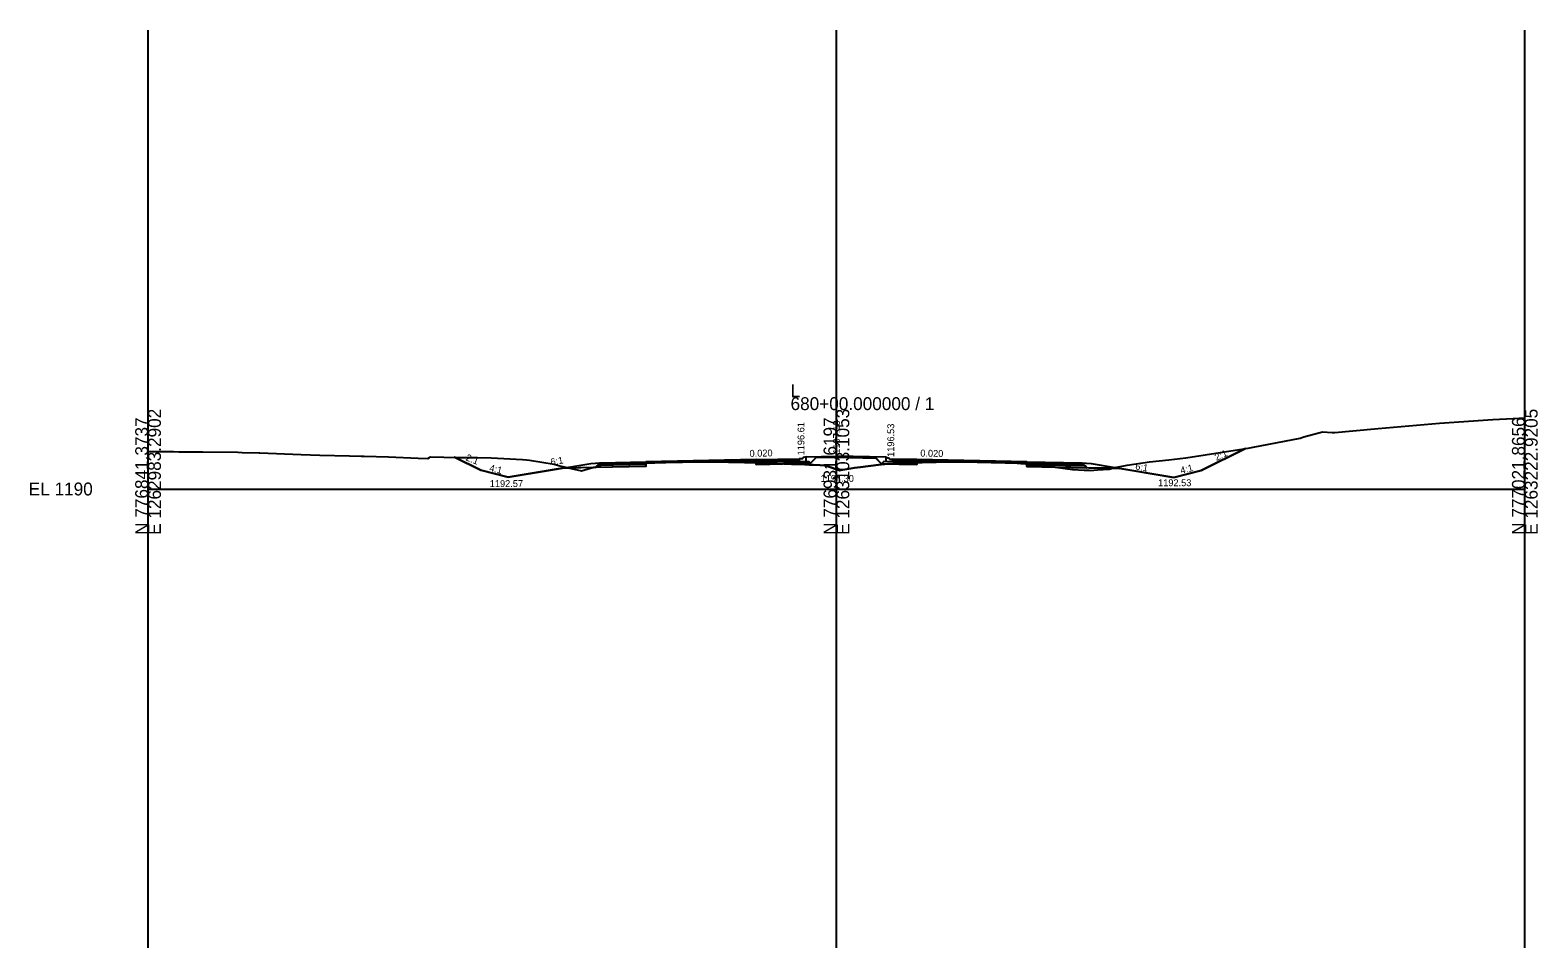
# Model space of a CAD drawing. Extents: x -41 to 1262860, y -100 to 777489.
# Drawn here: x 474.3 to 802.8, y 3185 to 3385 of the extents above; entities that cross this region are included whole.
import ezdxf

# ---------------------------------------------------------------- set-up
doc = ezdxf.new("R2010")
doc.units = 0
for name, color, linetype in [('Exist Cross Section Cell', 7, 'Continuous'), ('Exist XS Center Line Elevation Label', 7, 'Continuous'), ('Exist XS Ground Line', 7, 'Continuous'), ('Prop CMT Pvmt Course 1', 7, 'Continuous'), ('Prop CMT Pvmt Surface', 7, 'Continuous'), ('Prop CMT Shld Paved Course 1', 7, 'Continuous'), ('Prop CMT Shld Paved Course 2', 7, 'Continuous'), ('Prop CMT Shld Paved Course 4', 7, 'Continuous'), ('Prop CMT Subgrade Earthwork', 7, 'Continuous'), ('Prop Conc Curb and Gutter', 7, 'Continuous'), ('Prop Conc Island Cover', 7, 'Continuous'), ('Prop XS Ditch Standard Text', 7, 'Continuous'), ('Prop XS Earthwork Shape', 7, 'Continuous'), ('Prop XS Elevation Labels', 7, 'Continuous'), ('Prop XS Exc Vertical Line 1', 7, 'Continuous'), ('Prop XS Exc Vertical Line 2', 7, 'Continuous'), ('Prop XS Exc Vertical Line 3', 7, 'Continuous'), ('Prop XS Finish Grade', 7, 'Continuous'), ('Prop XS Hydro Elevations', 7, 'Continuous'), ('Prop XS SE Text', 7, 'Continuous'), ('Prop XS Side Slope Text', 7, 'Continuous'), ('Scratch_Level_4', 7, 'Continuous'), ('Scratch_Level_6', 7, 'Continuous')]:
    doc.layers.add(name, color=color, linetype=linetype)

msp = doc.modelspace()

# ---------------------------------------------------------------- linework, layer by layer
at = {"layer": 'Exist Cross Section Cell'}
for p, q in [((650, 3285), (650, 3305)), ((500, 3285), (650, 3285)), ((650, 3285), (800, 3285))]:
    msp.add_line(p, q, dxfattribs=at)
at = {"layer": 'Exist XS Ground Line'}
msp.add_lwpolyline([(500, 3293.17), (501.1, 3293.15), (502.01, 3293.14), (505.54, 3293.14), (506.73, 3293.13), (511.94, 3293.1), (519.57, 3293), (520.5, 3292.98), (524.21, 3292.89), (524.36, 3292.89), (533.39, 3292.5), (537.45, 3292.4), (543.89, 3292.26), (546.44, 3292.18), (547.08, 3292.16), (552.41, 3292.04), (558.87, 3291.75), (560.93, 3291.64), (561.35, 3291.9), (561.57, 3292.04), (567.36, 3291.9), (568.85, 3291.87), (569.19, 3291.86), (569.58, 3291.85), (571.79, 3291.83), (574.77, 3291.79), (581.6, 3291.44), (582.44, 3291.39), (583.1, 3291.3), (588.46, 3290.39), (589.76, 3290.03), (594.48, 3288.95), (595.92, 3289.38), (597.64, 3289.81), (599.6, 3290.57), (599.81, 3290.64), (600.51, 3290.63), (604.74, 3290.51), (605.11, 3290.43), (605.2, 3290.4), (609.59, 3290.73), (610.44, 3290.8), (612.8, 3290.84), (622.95, 3290.94), (631.36, 3290.74), (635.36, 3290.64), (640.2, 3290.43), (642.18, 3290.38), (644.08, 3290.3), (644.9, 3290.27), (646.48, 3290.18), (647.38, 3290.12), (647.97, 3289.95), (650.77, 3289.06), (651.4, 3289.2), (653.12, 3289.48), (653.92, 3289.63), (655.24, 3289.74), (659.16, 3290.28), (661.23, 3290.5), (664.55, 3290.67), (665.55, 3290.72), (674.84, 3290.89), (677.62, 3290.93), (686.8, 3290.69), (689.36, 3290.63), (690.18, 3290.58), (693.21, 3290.36), (695.59, 3290.03), (697.76, 3289.75), (699.84, 3289.47), (701.43, 3289.27), (703.96, 3289.12), (705, 3289.07), (705.3, 3289.05), (706.89, 3289.2), (709.41, 3289.34), (710.74, 3289.66), (713.33, 3290.21), (718.22, 3290.89), (722.45, 3291.37), (726.12, 3291.78), (738.75, 3293.79), (739.75, 3293.93), (740.83, 3294.14), (751.05, 3296.1), (751.87, 3296.34), (755.9, 3297.45), (758, 3297.34), (758.62, 3297.31), (762.55, 3297.69), (768.07, 3298.17), (781.4, 3299.34), (793.03, 3300.16), (797.48, 3300.36), (800, 3300.48)], dxfattribs=at)
at = {"layer": 'Prop CMT Pvmt Course 1'}
for p, q in [((632.5, 3291.16), (641.89, 3291.35)), ((641.89, 3291.35), (641.89, 3291.6)), ((662.3, 3291.51), (662.3, 3291.26)), ((667.5, 3291.16), (662.3, 3291.26))]:
    msp.add_line(p, q, dxfattribs=at)
for points in [[(608.5, 3290.93), (608.5, 3290.68), (632.5, 3291.16), (632.5, 3291.16), (632.5, 3291.41), (632.5, 3291.41), (632.5, 3291.41), (608.5, 3290.93), (608.5, 3290.93)], [(691.5, 3290.93), (691.5, 3290.93), (667.5, 3291.41), (667.5, 3291.41), (667.5, 3291.41), (667.5, 3291.16), (667.5, 3291.16), (691.5, 3290.68), (691.5, 3290.93)]]:
    msp.add_lwpolyline(points, dxfattribs=at)
at = {"layer": 'Prop CMT Pvmt Surface'}
for p, q in [((598.5, 3290.73), (608.5, 3290.93)), ((608.5, 3290.93), (632.5, 3291.41)), ((632.5, 3291.41), (641.89, 3291.6)), ((667.5, 3291.41), (662.3, 3291.51)), ((667.5, 3291.41), (691.5, 3290.93)), ((691.5, 3290.93), (703.5, 3290.69))]:
    msp.add_line(p, q, dxfattribs=at)
at = {"layer": 'Prop CMT Shld Paved Course 1'}
for p, q in [((598.24, 3290.47), (598.5, 3290.73)), ((608.5, 3290.68), (598.24, 3290.47)), ((604.5, 3290.85), (604.5, 3290.85)), ((608.5, 3290.93), (608.5, 3290.93)), ((608.5, 3290.93), (608.5, 3290.93)), ((608.5, 3290.93), (608.5, 3290.68)), ((608.5, 3290.68), (608.5, 3290.68)), ((691.5, 3290.93), (691.5, 3290.93)), ((691.5, 3290.93), (691.5, 3290.93)), ((691.5, 3290.93), (691.5, 3290.68)), ((691.5, 3290.68), (691.5, 3290.68)), ((691.5, 3290.68), (703.76, 3290.43)), ((695.5, 3290.85), (695.5, 3290.85)), ((703.76, 3290.43), (703.5, 3290.69))]:
    msp.add_line(p, q, dxfattribs=at)
at = {"layer": 'Prop CMT Shld Paved Course 2'}
for p, q in [((597.9, 3290.13), (598.24, 3290.47)), ((608.5, 3290.35), (597.9, 3290.13)), ((604.25, 3290.59), (604.25, 3290.59)), ((609.59, 3290.7), (608.5, 3290.68)), ((608.5, 3290.65), (609.05, 3290.69)), ((608.5, 3290.68), (608.5, 3290.68)), ((608.5, 3290.68), (608.5, 3290.68)), ((608.5, 3290.68), (608.5, 3290.35)), ((608.5, 3290.68), (608.5, 3290.68)), ((608.5, 3290.68), (608.5, 3290.65)), ((608.5, 3290.65), (608.5, 3290.65)), ((608.5, 3290.35), (608.5, 3290.35)), ((609.05, 3290.69), (609.59, 3290.7)), ((609.05, 3290.69), (609.05, 3290.69)), ((610.44, 3290.72), (609.59, 3290.7)), ((609.59, 3290.7), (610.44, 3290.72)), ((609.59, 3290.7), (609.59, 3290.7)), ((609.59, 3290.7), (609.59, 3290.7)), ((612.8, 3290.76), (610.44, 3290.72)), ((610.44, 3290.72), (612.8, 3290.76)), ((622.95, 3290.97), (612.8, 3290.76)), ((612.8, 3290.76), (619.95, 3290.91)), ((612.8, 3290.76), (612.8, 3290.76)), ((612.8, 3290.76), (612.8, 3290.76)), ((619.95, 3290.91), (622.95, 3290.94)), ((619.95, 3290.91), (619.95, 3290.91)), ((619.95, 3290.91), (619.95, 3290.91)), ((631.36, 3291.14), (622.95, 3290.97)), ((622.95, 3290.97), (622.95, 3290.97)), ((622.95, 3290.97), (622.95, 3290.97)), ((622.95, 3290.94), (622.95, 3290.94)), ((622.95, 3290.94), (629.95, 3290.77)), ((629.95, 3290.77), (631.36, 3290.8)), ((629.95, 3290.77), (629.95, 3290.77)), ((632.5, 3291.16), (631.36, 3291.14)), ((631.36, 3291.14), (631.36, 3291.14)), ((631.36, 3290.8), (632.5, 3290.83)), ((631.36, 3290.8), (631.36, 3290.8)), ((632.5, 3290.83), (632.5, 3291.16)), ((632.5, 3291.16), (632.5, 3291.16)), ((632.5, 3290.82), (641.89, 3291.01)), ((641.89, 3291.35), (641.89, 3291.01)), ((641.89, 3291.01), (641.89, 3291.01)), ((662.3, 3290.93), (662.3, 3291.26)), ((667.5, 3290.83), (662.3, 3290.93)), ((667.5, 3290.83), (667.5, 3291.16)), ((667.5, 3291.16), (667.5, 3291.16)), ((667.5, 3291.16), (667.5, 3291.16)), ((667.5, 3291.16), (674.84, 3291.01)), ((669.28, 3290.79), (667.5, 3290.83)), ((667.5, 3290.83), (667.5, 3290.83)), ((674.84, 3290.89), (669.28, 3290.79)), ((669.28, 3290.79), (669.28, 3290.79)), ((674.84, 3291.01), (674.84, 3291.01)), ((674.84, 3291.01), (677.62, 3290.96)), ((677.62, 3290.93), (674.84, 3290.89)), ((674.84, 3290.89), (674.84, 3290.89)), ((677.62, 3290.96), (677.62, 3290.96)), ((677.62, 3290.96), (686.8, 3290.77)), ((686.8, 3290.69), (677.62, 3290.93)), ((677.62, 3290.93), (677.62, 3290.93)), ((686.8, 3290.77), (686.8, 3290.77)), ((686.8, 3290.77), (689.36, 3290.72)), ((689.36, 3290.63), (686.8, 3290.69)), ((686.8, 3290.69), (686.8, 3290.69)), ((689.36, 3290.72), (690.18, 3290.7)), ((690.18, 3290.58), (689.36, 3290.63)), ((690.18, 3290.7), (690.18, 3290.7)), ((690.18, 3290.7), (691.5, 3290.68)), ((691.5, 3290.48), (690.18, 3290.58)), ((690.18, 3290.58), (690.18, 3290.58)), ((691.5, 3290.68), (691.5, 3290.68)), ((691.5, 3290.68), (691.5, 3290.68)), ((691.5, 3290.68), (691.5, 3290.35)), ((691.5, 3290.68), (691.5, 3290.68)), ((691.5, 3290.68), (691.5, 3290.68)), ((691.5, 3290.68), (691.5, 3290.48)), ((691.5, 3290.48), (691.5, 3290.48)), ((691.5, 3290.35), (691.5, 3290.35)), ((691.5, 3290.35), (704.1, 3290.09)), ((704.1, 3290.09), (703.76, 3290.43))]:
    msp.add_line(p, q, dxfattribs=at)
at = {"layer": 'Prop CMT Shld Paved Course 4'}
for p, q in [((597.9, 3290.13), (597.44, 3289.67)), ((608.5, 3289.89), (597.44, 3289.67)), ((603.41, 3290.24), (603.41, 3290.24)), ((603.91, 3290.25), (603.91, 3290.25)), ((608.5, 3290.35), (608.5, 3290.35)), ((608.5, 3290.35), (608.5, 3290.35)), ((608.5, 3290.35), (608.5, 3289.89)), ((629.95, 3290.77), (631.36, 3290.74)), ((631.36, 3290.74), (632.5, 3290.71)), ((632.5, 3290.83), (632.5, 3290.37)), ((632.5, 3290.37), (644.34, 3290.6)), ((641.89, 3291.01), (643.89, 3291.05)), ((643.89, 3291.05), (644.34, 3290.6)), ((660.3, 3290.97), (659.85, 3290.52)), ((667.5, 3290.37), (659.85, 3290.52)), ((662.3, 3290.93), (660.3, 3290.97)), ((667.5, 3290.83), (667.5, 3290.37)), ((669.28, 3290.79), (667.5, 3290.76)), ((691.5, 3290.35), (691.5, 3290.35)), ((691.5, 3290.35), (691.5, 3290.35)), ((691.5, 3290.35), (691.5, 3289.89)), ((691.5, 3289.89), (704.56, 3289.63)), ((704.56, 3289.63), (704.1, 3290.09))]:
    msp.add_line(p, q, dxfattribs=at)
at = {"layer": 'Prop CMT Subgrade Earthwork'}
for p, q in [((644.34, 3290.6), (645.83, 3292.09)), ((659.85, 3290.52), (658.36, 3292.01)), ((608.5, 3289.89), (590.22, 3289.52)), ((608.5, 3289.89), (608.5, 3290.65)), ((632.5, 3290.37), (632.5, 3290.71)), ((644.34, 3290.6), (632.5, 3290.37)), ((659.85, 3290.52), (667.5, 3290.37)), ((667.5, 3290.37), (667.5, 3290.76)), ((691.5, 3290.48), (691.5, 3289.89)), ((691.5, 3289.89), (711.78, 3289.48))]:
    msp.add_line(p, q, dxfattribs=at)
at = {"layer": 'Prop Conc Curb and Gutter'}
for p, q in [((643.39, 3292.04), (642.74, 3291.83)), ((643.39, 3291.04), (643.39, 3292.04)), ((660.8, 3291.96), (661.45, 3291.74)), ((660.8, 3290.96), (660.8, 3291.96)), ((641.89, 3291.6), (641.89, 3291.01)), ((642.58, 3291.61), (641.89, 3291.6)), ((641.89, 3291.01), (643.39, 3291.04)), ((642.65, 3291.69), (642.65, 3291.67)), ((643.39, 3291.04), (643.39, 3291.04)), ((662.3, 3290.93), (660.8, 3290.96)), ((661.55, 3291.6), (661.55, 3291.59)), ((661.61, 3291.53), (662.3, 3291.51)), ((662.3, 3290.93), (662.3, 3291.51))]:
    msp.add_line(p, q, dxfattribs=at)
for centre, radius, start, end in [((642.58, 3291.67), 0.0625, 271.1458, 360), ((642.79, 3291.69), 0.146, 108.435, 180), ((661.4, 3291.6), 0.146, 0, 71.565), ((661.61, 3291.59), 0.0625, 180, 268.8542)]:
    msp.add_arc(centre, radius, start, end, dxfattribs=at)
at = {"layer": 'Prop Conc Island Cover'}
for p, q in [((643.39, 3292.04), (650, 3292.18)), ((660.8, 3291.96), (650, 3292.18)), ((643.39, 3291.78), (643.39, 3291.78))]:
    msp.add_line(p, q, dxfattribs=at)
at = {"layer": 'Prop XS Earthwork Shape'}
for points in [[(582.44, 3291.39), (583.1, 3291.3), (588.46, 3290.39), (589.76, 3290.03), (591.25, 3289.69), (590.22, 3289.52), (578.5, 3287.57), (572.5, 3289.07), (566.8, 3291.92), (567.36, 3291.9), (568.85, 3291.87), (569.19, 3291.86), (569.58, 3291.85), (571.79, 3291.83), (574.77, 3291.79), (581.6, 3291.44)], [(645.58, 3291.84), (650, 3291.93), (658.61, 3291.75), (659.85, 3290.52), (661.15, 3290.49), (659.16, 3290.28), (655.24, 3289.74), (653.92, 3289.63), (653.12, 3289.48), (651.4, 3289.2), (650.77, 3289.06), (647.97, 3289.95), (647.38, 3290.12), (646.48, 3290.18), (644.9, 3290.27), (644.08, 3290.3), (642.18, 3290.38), (640.2, 3290.43), (638.7, 3290.49), (644.34, 3290.6)], [(713.33, 3290.21), (718.22, 3290.89), (722.45, 3291.37), (726.12, 3291.78), (738.75, 3293.79), (739.13, 3293.85), (729.5, 3289.03), (723.5, 3287.53), (711.78, 3289.48), (710.73, 3289.66), (710.74, 3289.66)], [(591.25, 3289.69), (591.85, 3289.55), (590.22, 3289.52)], [(597.02, 3289.66), (591.85, 3289.55), (594.48, 3288.95), (595.92, 3289.38)], [(597.57, 3289.79), (597.44, 3289.67), (597.02, 3289.66)], [(604.74, 3290.51), (605.11, 3290.43), (605.2, 3290.4), (608.5, 3290.65), (608.5, 3289.89), (597.44, 3289.67), (597.57, 3289.79), (597.64, 3289.81), (599.6, 3290.57), (599.81, 3290.64), (600.51, 3290.63)], [(635.36, 3290.64), (638.7, 3290.49), (632.5, 3290.37), (632.5, 3290.71)], [(661.15, 3290.49), (667.5, 3290.37), (667.5, 3290.76), (665.55, 3290.72), (664.55, 3290.67), (661.23, 3290.5)], [(695.59, 3290.03), (697.66, 3289.76), (691.5, 3289.89), (691.5, 3290.48), (693.21, 3290.36)], [(701.43, 3289.27), (703.96, 3289.12), (705, 3289.07), (705.3, 3289.05), (706.89, 3289.2), (709.41, 3289.34), (710.14, 3289.51), (704.56, 3289.63), (697.66, 3289.76), (697.76, 3289.75), (699.84, 3289.47)], [(710.14, 3289.51), (711.78, 3289.48), (710.73, 3289.66)]]:
    msp.add_lwpolyline(points, close=True, dxfattribs=at)
at = {"layer": 'Prop XS Exc Vertical Line 1'}
msp.add_line((500, 3185), (500, 3385), dxfattribs=at)
at = {"layer": 'Prop XS Exc Vertical Line 2'}
msp.add_line((650, 3185), (650, 3385), dxfattribs=at)
at = {"layer": 'Prop XS Exc Vertical Line 3'}
msp.add_line((800, 3185), (800, 3385), dxfattribs=at)
at = {"layer": 'Prop XS Finish Grade'}
for p, q in [((566.8, 3291.92), (572.5, 3289.07)), ((729.5, 3289.03), (739.13, 3293.85)), ((572.5, 3289.07), (578.5, 3287.57)), ((578.5, 3287.57), (596.5, 3290.57)), ((596.5, 3290.57), (598.5, 3290.73)), ((598.5, 3290.73), (597.44, 3289.67)), ((703.5, 3290.69), (705.5, 3290.53)), ((703.5, 3290.69), (704.56, 3289.63)), ((705.5, 3290.53), (723.5, 3287.53)), ((723.5, 3287.53), (729.5, 3289.03))]:
    msp.add_line(p, q, dxfattribs=at)
at = {"layer": 'Scratch_Level_4'}
msp.add_line((800, 3185), (800, 3385), dxfattribs=at)
at = {"layer": 'Scratch_Level_6'}
msp.add_line((500, 3185), (500, 3385), dxfattribs=at)

# ---------------------------------------------------------------- texts
at = {"layer": 'Exist Cross Section Cell'}
for s, p in [('680+00.000000 / 1', (640, 3302.2)), ('L', (640, 3305)), ('EL 1190', (474, 3283.6))]:
    msp.add_text(s, height=2.8, dxfattribs=at).set_placement(p)
for s, p in [('E 1262983.2902', (502.8, 3275)), ('E 1263103.1053', (652.8, 3275)), ('E 1263222.9205', (802.8, 3275)), ('N 776841.3737', (500, 3275)), ('N 776931.6197', (650, 3275)), ('N 777021.8656', (800, 3275))]:
    msp.add_text(s, height=2.8, rotation=90, dxfattribs=at).set_placement(p)
at = {"layer": 'Exist XS Center Line Elevation Label'}
msp.add_text('1194.30', height=1.5, dxfattribs=at).set_placement((646.55, 3286.55))
at = {"layer": 'Prop XS Ditch Standard Text'}
for s, p in [('1192.57', (574.46, 3285.43)), ('1192.53', (720.09, 3285.61))]:
    msp.add_text(s, height=1.5, dxfattribs=at).set_placement(p)
at = {"layer": 'Prop XS Elevation Labels'}
for s, p in [('1196.61', (643.03, 3292.33)), ('1196.53', (662.59, 3291.99))]:
    msp.add_text(s, height=1.5, rotation=90, dxfattribs=at).set_placement(p)
at = {"layer": 'Prop XS Hydro Elevations'}
msp.add_text('1197.18', height=1.5, rotation=90, dxfattribs=at).set_placement((650.77, 3292.68))
at = {"layer": 'Prop XS SE Text'}
for rotation, p in [(1.1458, (631.08, 3292.01)), (358.8542, (668.26, 3292.08))]:
    msp.add_text('0.020', height=1.5, rotation=rotation, dxfattribs=at).set_placement(p)
at = {"layer": 'Prop XS Side Slope Text'}
for s, rotation, p in [('2:1', 338.2726, (569.08, 3291.29)), ('6:1', 9.4623, (587.83, 3290.13)), ('2:1', 24.7387, (732.82, 3291.11)), ('4:1', 345.9638, (574.25, 3288.94)), ('6:1', 350.5377, (715.03, 3289.26)), ('4:1', 14.0362, (725.13, 3288.28))]:
    msp.add_text(s, height=1.5, rotation=rotation, dxfattribs=at).set_placement(p)

doc.saveas('drawing.dxf')
